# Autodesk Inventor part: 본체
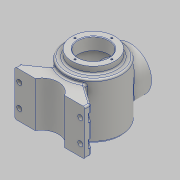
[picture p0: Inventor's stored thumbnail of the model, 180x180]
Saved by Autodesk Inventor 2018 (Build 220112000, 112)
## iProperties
Created: 2021-04
Part Number: 본체
Material: 알루미늄 6061
Document SubType Name: Modeling
Designer: home
Density: 2.7 g/cm^3
Appearance: 알루미늄 - 평지
Mass: 608.117 g
Surface Area: 1038.73 cm^2
Volume: 608.117 cm^3
Author: home
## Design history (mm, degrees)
sketch "스케치1"
  geometry: L1 (0, 60)-(0, -60); L2 (0, 60)-(27, 60); L3 (38, 60)-(38, 48); L4 (38, 48)-(50, 48); L5 (50, -48.336)-(50, 48); L6 (27, 60)-(27, 38); L7 (27, 60)-(38, 60); L8 (40, -41.916)-(40, 38); L9 (40, 38)-(27, 38); L10 (0, -50)-(0, -60); A1 r 113 centre (0, 53) between (0, -60) and (50, -48.336); A2 r 103 centre (0, 53) between (0, -50) and (40, -41.916); 2 further points
  constraints: 20 end point, 4 perpendicular, 4 point on circle, 3 vertical, 2 centre point, 2 horizontal, 1 coincident, 1 collinear, 1 midpoint, 1 point on line, 1 other
  dimensions: "d0" = 120 distance of L1.start L1.end; "d1" = 38 distance of L1.start L3.start; "d2" = 12 distance of L3.start L3.end; "d5" = 226 diameter of A1; "d6" = 50 distance between parallel lines of L1 L5; "d7" = 22 distance of L2.end L6.end; "d8" = 54 diameter of L6 L1; "d10" = 10 radial gap between concentric circles of A1 A2
revolve "회전1" sketch "스케치1" stored, may be unused: angle "d11" = 90 deg
node "작업 평면3"
  node "작업 평면2"
sketch "스케치4"
  geometry: L1 (-62, -77)-(-25.981, -77); L2 (62, -77)-(62, -67); L3 (62, -67)-(26.694, -42.278); L4 (0, -77)-(0, -62); L5 (-25.981, -77)-(25.981, -77); L6 (25.981, -77)-(62, -77); L7 (-62, -67)-(-26.694, -42.278); L8 (-62, -77)-(-62, -67); A1 r 50 centre (0, 0) between (26.694, -42.278) and (-26.694, -42.278) reference; A2 r 30 centre (0, -92) between (25.981, -77) and (-25.981, -77); A3 r 50 centre (0, 0) between (-26.694, -42.278) and (26.694, -42.278); 3 further points
  constraints: 16 end point, 8 point on circle, 3 horizontal, 3 vertical, 2 centre point, 2 vertical alignment, 1 coincident, 1 concentric, 1 midpoint, 1 point on line
  dimensions: "d23" = 77 distance from line of L1 point (0, 0); "d24" = 10 distance of L2.start L2.end; "d25" = 55 deg angle of L2 L3; "d27" = 60 diameter of A2; "d32" = 77 distance of L4.start point (0, 0); "d33" = 62 distance from line of L4.start L8; "d34" = 124 distance between parallel lines of L2 L8; "d39" = 19.32145 distance from line of point (0, 0) L7; "d41" = 62 distance from line of point (0, -62) L2; "d42" = 55 deg angle of L7 L8; "d43" = 15 distance of L4.end L4.start
extrude "돌출3" join sketch "스케치4" distance "d30" = 80; taper "d31" = 0 deg
sketch "스케치5"
  geometry: L1 (36.019, 0)-(36.019, -80) reference; L2 (0, 0)-(36.019, 0) reference; C1 r 4.5 at (28.019, -20); 1 further point
  constraints: 1 centre point
  dimensions: "d44" = 9 diameter of C1; "d45" = 8 distance from line of L1 C1.centre; "d46" = 20 distance from line of L2 C1.centre
extrude "돌출4" cut sketch "스케치5" distance "d47" = 20; taper "d48" = 0 deg
node "작업 평면5"
sketch "스케치7"
  geometry: L1 (-54, 13)-(-62, 13); L2 (-54, 27)-(-62, 27); L3 (-62, 13)-(-62, 27); C1 r 4.5 at (-54, 20) reference; A1 r 7 centre (-54, 20) between (-54, 13) and (-54, 27); A2 r 7 centre (-54, 20) between (-54, 27) and (-54, 13); 1 further point
  constraints: 6 end point, 4 point on circle, 2 centre point, 2 horizontal, 2 tangent, 1 coincident, 1 vertical
  dimensions: "d54" = 14 diameter of A1; "d55" = 8 distance from line of L3 C1.centre
extrude "돌출6" cut sketch "스케치7" distance "d56" = 20; taper "d57" = 0 deg
sketch "스케치8" dims "d58" = 65
  geometry: 3 further points
  constraints: 2 vertical alignment, 1 coincident, 2 other
hole "구멍1" sketch "스케치8" at (0, 32.5) diameter "d59" = 3.242; stored, may be unused: countersink angle "d63" = 90 deg, drill point angle "d65" = 118 deg; dims "d60" = 8, "d61" = 4, "d62" = 2, "d64" = 10
fillet "모깎기1" dims "d82" = 3
fillet "모깎기2" dims "d83" = 3
fillet "모깎기3" dims "d84" = 3
chamfer "모따기1" distance "d86" = 1; stored, may be unused: second distance "d87" = 2, angle "d88" = 45 deg
fillet "모깎기4" dims "d89" = 3
fillet "모깎기5" dims "d90" = 3
node "작업 평면9"
sketch "스케치12"
  geometry: L1 (-38, 60)-(38, 60) reference; C1 r 38 at (0, -2); 1 further point
  constraints: 1 centre point, 1 vertical alignment
  dimensions: "d92" = 76 diameter of C1; "d93" = 62 distance from line of L1 C1.centre
extrude "돌출7" join sketch "스케치12" stored distance "d94" = 20; taper "d95" = 0 deg
sketch "스케치13"
  geometry: C1 r 38 at (0, 0) reference; C2 r 27 at (0, 0); 1 further point
  constraints: 1 centre point, 1 coincident
  dimensions: "d96" = 54 diameter of C2
extrude "돌출8" cut sketch "스케치13" stored distance "d97" = 20; taper "d98" = 0 deg
sketch "스케치14" dims "d99" = 65
  geometry: C1 r 27 at (0, 0) reference; C2 r 38 at (0, 0) reference; 3 further points
  constraints: 2 horizontal alignment, 1 coincident, 2 other
hole "구멍3" sketch "스케치14" at (-32.5, 0) diameter "d100" = 3.242; stored, may be unused: countersink angle "d104" = 90 deg, drill point angle "d106" = 118 deg; dims "d101" = 8, "d102" = 4, "d103" = 2, "d105" = 10
fillet "모깎기6" dims "d110" = 3
chamfer "모따기2" distance "d111" = 1; stored, may be unused: second distance "d112" = 2, angle "d113" = 45 deg
node "작업 평면12"
sketch "스케치19"
  geometry: 2 further points
  constraints: 2 coincident, 1 other
feature "엠보싱1" sketch "스케치19" dims "d23" = 77, "d24" = 10, "d25" = 55 deg, "d27" = 60, "d32" = 77, "d33" = 62, "d34" = 124, "d39" = 19.32145, "d41" = 62, "d42" = 55 deg, "d43" = 15, "d116" = 0.5, "d117" = 0
node "솔리드1"
mirror "미러1"
mirror "미러2"
pattern_circular "원형 패턴1" dims angle "d67" = 360 deg
pattern_circular "원형 패턴3" dims angle "d108" = 360 deg
node "투영된 루프1"
node "투영된 루프3"
node "투영된 루프4"
other parameters: "d53" = -71, "d91" = 65
